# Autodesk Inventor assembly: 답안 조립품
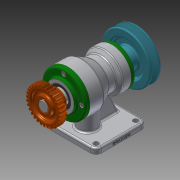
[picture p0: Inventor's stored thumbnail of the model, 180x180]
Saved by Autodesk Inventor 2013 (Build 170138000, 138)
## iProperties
Created: 2019-01
Part Number: 답안 조립품
Document SubType Name: Assembly
Designer: Administrator
Author: Administrator
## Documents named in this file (15)
- C:\Users\Administrator\Desktop\490107V1042\답안 조립품.iam
- C:\Users\Administrator\Desktop\490107V1042\본체.ipt
- C:\Users\Administrator\Desktop\490107V1042\V-벨트풀리.ipt
- C:\Users\Administrator\Desktop\490107V1042\뒤커버.ipt
- C:\Users\Administrator\Desktop\490107V1042\멈춤나사 M3.ipt
- C:\Users\Administrator\Desktop\490107V1042\베어링 6203.ipt
- C:\Users\Administrator\Desktop\490107V1042\베어링 6205.ipt
- C:\Users\Administrator\Desktop\490107V1042\볼트 M4.ipt
- C:\Users\Administrator\Desktop\490107V1042\스퍼기어.ipt
- C:\Users\Administrator\Desktop\490107V1042\앞커버.ipt
- C:\Users\Administrator\Desktop\490107V1042\오일 실 17 30 8.ipt
- C:\Users\Administrator\Desktop\490107V1042\오일 실 25 38 8.ipt
- C:\Users\Administrator\Desktop\490107V1042\축.ipt
- C:\Users\Administrator\Desktop\490107V1042\키 5 x 5 x 20.ipt
- C:\Users\Administrator\Desktop\490107V1042\키 6 x 6 x 18.ipt
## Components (1 placed, 1 different names)
1. V-벨트풀리:1 — 플러쉬:1
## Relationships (1: Flush 1)
- 플러쉬:1 [Flush]: V-벨트풀리:1
